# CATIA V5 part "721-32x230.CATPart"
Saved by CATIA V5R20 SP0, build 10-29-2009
Part number: 721-32x230
Definition: NONE
Nomenclature: 721-32x230
Source: Unknown
Description: 721-32x230
Bounding box of the stored display mesh (mm): x -100 to 130, y -30 to 30, z -30 to 30
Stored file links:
  C:\Users\Utente\Desktop\IO LAVORO\3D X SITO CF\X SITO\721\721-32x230.CATPart
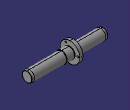
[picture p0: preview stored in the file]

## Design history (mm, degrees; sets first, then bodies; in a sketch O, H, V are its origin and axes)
Body1 "721-32x230" (main body)
  Solid1: solid without history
